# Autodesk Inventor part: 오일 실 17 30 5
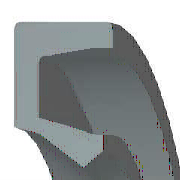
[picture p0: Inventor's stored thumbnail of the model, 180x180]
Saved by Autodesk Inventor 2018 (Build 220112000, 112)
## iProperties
IsCustomPart: 1
Created: 2012-02
Part Number: 오일 실 17 30 5
Material: 고무
Description: 오일 실 - 비스프링, 금속 케이스 GM
Document SubType Name: Modeling
Standard: JIS B 2402
Designer: mduedu
Standards Organization: JIS
Language: ko-KR
Size Designation: 17 30 5 B
Categories: <MemberInstance><Categories><Category DisplayName="샤프트 부품" InternalName="7f7aeb1f-a693-4053-b835-cee3144e0d98" Mnemonic="SHFT"><Category DisplayName="실링" Intern
Density: 0.93 g/cm^3
Appearance: Rubber-Black
Author: mduedu
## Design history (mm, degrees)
body "Solid1"
revolve "회전1" stored, may be unused: angle "d27" = 360 deg
fillet "모깎기1" dims "d28" = 0.25 (= 0.05 x b)
chamfer "모따기1" distance "d29" = 0.07143 (= 0.0142857 x b); stored, may be unused: second distance "d30" = 0.25 (= 0.05 x b), angle "d35" = 45 deg
sketch "스케치2"
  geometry: L1 (-9.367, -3.238)-(-10.233, -3.863); L2 (-8.5, -1.625)-(-9.367, -3.238); L3 (-9.15, -1)-(-8.5, -1.625); L4 (-11.317, -3.75)-(-9.15, -1); L5 (-13.075, -3.75)-(-11.317, -3.75); L6 (-14.375, -1.25)-(-13.075, -3.75); L7 (-14.375, 0)-(-14.375, -1.25); L8 (-15, 0)-(-14.375, 0); L9 (-15, -5)-(-15, 0); L10 (-11.129, -5)-(-15, -5); L11 (-10.233, -3.863)-(-11.129, -5); L12 (0, -9.6)-(0, 1.6) reference; L13 (-14, 0)-(-28, 0) reference
  constraints: 22 end point, 3 horizontal, 2 vertical, 1 parallel
  dimensions: "d2" = 5 distance of L9.start L8.start (= b); "d4" = 1 vertical distance of L8.start L3.start (= 0.2 x b); "d6" = 0.625 distance of L8.start L7.start (= 0.125 x b); "d8" = 1.25 distance of L7.start L6.start (= 0.25 x b); "d10" = 1.25 vertical distance of L5.start L9.start (= 0.25 x b); "d12" = 1.3 horizontal distance of L6.start L5.start (= 0.1 x dd - 0.1 x Diam); "d14" = 1.6129 vertical distance of L2.start L1.start (= 0.322581 x b); "d16" = 0.86667 horizontal distance of L1.start L1.end (= 0.0666667 x dd - 0.0666667 x Diam); "d18" = 0.86667 horizontal distance of L2.start L1.start (= 0.0666667 x dd - 0.0666667 x Diam); "d20" = 0.625 vertical distance of L3.start L2.start (= 0.125 x b); "d22" = 0.65 horizontal distance of L3.start L2.start (= 0.05 x dd - 0.05 x Diam); "d24" = 0.625 vertical distance of L1.start L1.end (= 0.125 x b); "d26" = 2.16667 horizontal distance of L4.start L3.start (= 0.166667 x dd - 0.166667 x Diam); "d31" = 0 distance between parallel lines of L8 L13; "d32" = 15 distance between parallel lines of L12 L9 (= 0.5 x dd); "d33" = 8.5 distance from line of L12 L2.start (= 0.5 x Diam)
other parameters: "Diam" = 17 [user parameter; used in 6 equation terms], "b" = 5 [user parameter; used in 11 equation terms], "d1" = 8 (derived), "d3" = 1.6 (derived), "d5" = 1 (derived), "d7" = 2 (derived), "d9" = 2 (derived), "d11" = 2 (derived), "d13" = 2.58065 (derived), "d15" = 1.33333 (derived), "d17" = 1.33333 (derived), "d19" = 1 (derived), "d21" = 1 (derived), "d23" = 1 (derived), "d25" = 3.33333 (derived), "d34" = 0
